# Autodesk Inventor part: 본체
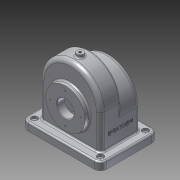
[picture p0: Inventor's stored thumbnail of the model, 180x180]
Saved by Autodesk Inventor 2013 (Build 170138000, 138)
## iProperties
Created: 2017-11
Part Number: 본체
Material: 알루미늄 6061
Document SubType Name: Modeling
Designer: Administrator
Density: 2.71 g/cm^3
Mass: 1117.61 g
Surface Area: 1185.63 cm^2
Volume: 412.401 cm^3
Author: Administrator
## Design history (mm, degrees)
sketch "스케치1"
  geometry: L1 (-58, 0)-(-58, -65); L2 (58, 0)-(58, -65); L3 (-58, -65)-(58, -65); A1 r 58 centre (0, 0) between (58, 0) and (-58, 0); 1 further point
  constraints: 6 end point, 2 point on circle, 2 tangent, 1 centre point, 1 coincident, 1 parallel, 1 vertical
  dimensions: "d0" = 116 diameter of A1; "d2" = 65 distance of L1.start L1.end; "d3" = 65 distance of L2.start L2.end
extrude "돌출1" new body sketch "스케치1" stored distance "d4" = 38; taper "d5" = 0 deg
sketch "스케치2"
  geometry: L1 (-58, -23)-(-58, -65); L2 (58, -23)-(58, -65); L3 (-58, -65)-(58, -65); L4 (-58, -65)-(58, -65) reference; A1 r 58 centre (0, 0) between (58, 0) and (-58, 0) reference; A2 r 58 centre (0, -23) between (58, -23) and (-58, -23); 1 further point
  constraints: 6 end point, 2 point on circle, 2 tangent, 1 centre point, 1 collinear, 1 parallel, 1 perpendicular, 1 vertical, 1 vertical alignment
  dimensions: "d6" = 116 diameter of A2; "d7" = 42 distance of L1.start L1.end
extrude "돌출2" join sketch "스케치2" distance "d8" = 38; taper "d9" = 0 deg
sketch "스케치3"
  geometry: L1 (-58, -65)-(58, -65) reference; C1 r 37.5 at (0, -15); 1 further point
  constraints: 1 centre point, 1 vertical alignment
  dimensions: "d10" = 75 diameter of C1; "d11" = 50 distance from line of C1.centre L1
feature "쉘1" dims "d12" = 5
extrude "돌출3" join sketch "스케치3" distance "d13" = 9; taper "d14" = 0 deg
sketch "스케치4"
  geometry: C1 r 31 at (0, -15); C2 r 37.5 at (0, -15) reference; 1 further point
  constraints: 1 centre point, 1 concentric
  dimensions: "d84" = 62 diameter of C1
extrude "돌출4" join sketch "스케치4" distance "d15" = 10; taper "d16" = 0 deg
sketch "스케치5"
  geometry: C1 r 16 at (0, 0); C2 r 37.5 at (0, 0) reference; 1 further point
  constraints: 1 centre point, 1 concentric
  dimensions: "d17" = 32 diameter of C1
extrude "돌출5" cut sketch "스케치5" stored distance "d18" = 10; taper "d19" = 0 deg
sketch "스케치6"
  geometry: C1 r 16 at (0, 0) reference; 2 further points
  constraints: 1 vertical alignment
  dimensions: "d20" = 29 distance of C1.centre point (0, 29)
hole "구멍1" sketch "스케치6" at (0, 29) diameter "d21" = 2.459; stored, may be unused: countersink angle "d25" = 90 deg, drill point angle "d27" = 118 deg; dims "d22" = 6, "d23" = 4, "d24" = 2, "d26" = 8
node "작업 평면1"
node "작업 평면3"
  node "작업 평면2"
sketch "스케치7"
  geometry: C1 r 6 at (0, 0); 1 further point
  constraints: 1 centre point, 1 coincident
  dimensions: "d32" = 12 diameter of C1
extrude "돌출6" join sketch "스케치7" stored distance "d34" = 10; taper "d35" = 0 deg
sketch "스케치8"
  geometry: 2 further points
  constraints: 1 coincident
hole "구멍2" sketch "스케치8" at (0, 0) diameter "d36" = 4.459; stored, may be unused: countersink angle "d40" = 90 deg, drill point angle "d42" = 118 deg; dims "d37" = 20, "d38" = 4, "d39" = 2, "d41" = 8
sketch "스케치9"
  geometry: L1 (-17, 17)-(133, 17); L2 (133, 17)-(133, -93); L3 (133, -93)-(-17, -93); L4 (-17, -93)-(-17, 17); L5 (0, 0)-(116, 0) reference; L6 (0, -76)-(0, 0) reference; L7 (116, -76)-(116, 0) reference; L8 (116, -76)-(0, -76) reference; L9 (111, -33)-(5, -33) reference; L10 (116, -38)-(0, -38) reference; 1 further point
  constraints: 8 end point, 2 parallel, 1 horizontal, 1 perpendicular
  dimensions: "d43" = 110 distance of L1.end L2.end; "d45" = 150 distance of L1.start L1.end; "d47" = 55 distance between parallel lines of L10 L1; "d48" = 75 distance from line of L4 point (58, -19)
extrude "돌출7" join sketch "스케치9" distance "d49" = 15; taper "d50" = 0 deg
fillet "모깎기1" dims "d51" = 12
sketch "스케치10"
  geometry: A1 r 12 centre (-5, 81) between (-5, 93) and (-17, 81) reference; A2 r 12 centre (121, 81) between (133, 81) and (121, 93) reference; A3 r 12 centre (121, 81) between (133, 81) and (121, 93) reference; A4 r 12 centre (121, -5) between (121, -17) and (133, -5) reference; A5 r 12 centre (121, -5) between (121, -17) and (133, -5) reference; A6 r 12 centre (-5, -5) between (-17, -5) and (-5, -17) reference; 5 further points
  constraints: 4 coincident
hole "구멍3" sketch "스케치10" at (-5, 81), (-5, -5), (121, -5), (121, 81) diameter "d52" = 5; stored, may be unused: countersink angle "d56" = 90 deg, drill point angle "d58" = 118 deg; dims "d53" = 6, "d54" = 12, "d55" = 5, "d57" = 8
fillet "모깎기2" dims "d59" = 3
sketch "스케치11"
  geometry: L1 (111, -8)-(111, -68) reference; L2 (108, -71)-(8, -71) reference; L3 (5, -68)-(5, -8) reference; L4 (8, -5)-(108, -5) reference; L5 (116, -76)-(116, 0) reference; L6 (0, 0)-(116, 0) reference; L7 (0, -76)-(0, 0) reference; L8 (116, -76)-(0, -76) reference; A1 r 3 centre (108, -68) between (108, -71) and (111, -68) reference; A2 r 3 centre (8, -68) between (5, -68) and (8, -71) reference; A3 r 3 centre (8, -8) between (8, -5) and (5, -8) reference; A4 r 3 centre (108, -8) between (111, -8) and (108, -5) reference; 1 further point
extrude "돌출8" join sketch "스케치11" distance "d60" = 15; taper "d61" = 0 deg
fillet "모깎기3" dims "d62" = 8
fillet "모깎기4" dims "d63" = 3
chamfer "모따기1" distance "d64" = 1; stored, may be unused: second distance "d65" = 2, angle "d66" = 45 deg
fillet "모깎기5" dims "d67" = 3
node "작업 평면4"
sketch "스케치12"
  geometry: L1 (73, -18)-(-13, -18) reference; L2 (-8, 62)-(-8, 0) reference; 2 further points
  constraints: 1 other
  dimensions: "d69" = 40 distance from line of L1 point (30, 22); "d70" = 38 distance from line of point (30, 22) L2
feature "엠보싱1" sketch "스케치12" dims "d0" = 116, "d2" = 65, "d3" = 65, "d10" = 75, "d11" = 50, "d71" = 0.5, "d72" = 0
sketch "스케치13"
  geometry: C1 r 31 at (0, 0) reference; 2 further points
  constraints: 1 vertical alignment
  dimensions: "d73" = 26 distance of C1.centre point (0, 26)
hole "구멍4" sketch "스케치13" at (0, 26) diameter "d74" = 2.459; stored, may be unused: countersink angle "d78" = 90 deg, drill point angle "d80" = 118 deg; dims "d75" = 6, "d76" = 12, "d77" = 5, "d79" = 8
node "솔리드1"
pattern_circular "원형 패턴1" dims angle "d29" = 360 deg
pattern_circular "원형 패턴2" dims angle "d82" = 360 deg
node "투영된 루프1"
node "투영된 루프2"
node "투영된 루프3"
other parameters: "d31" = 6
